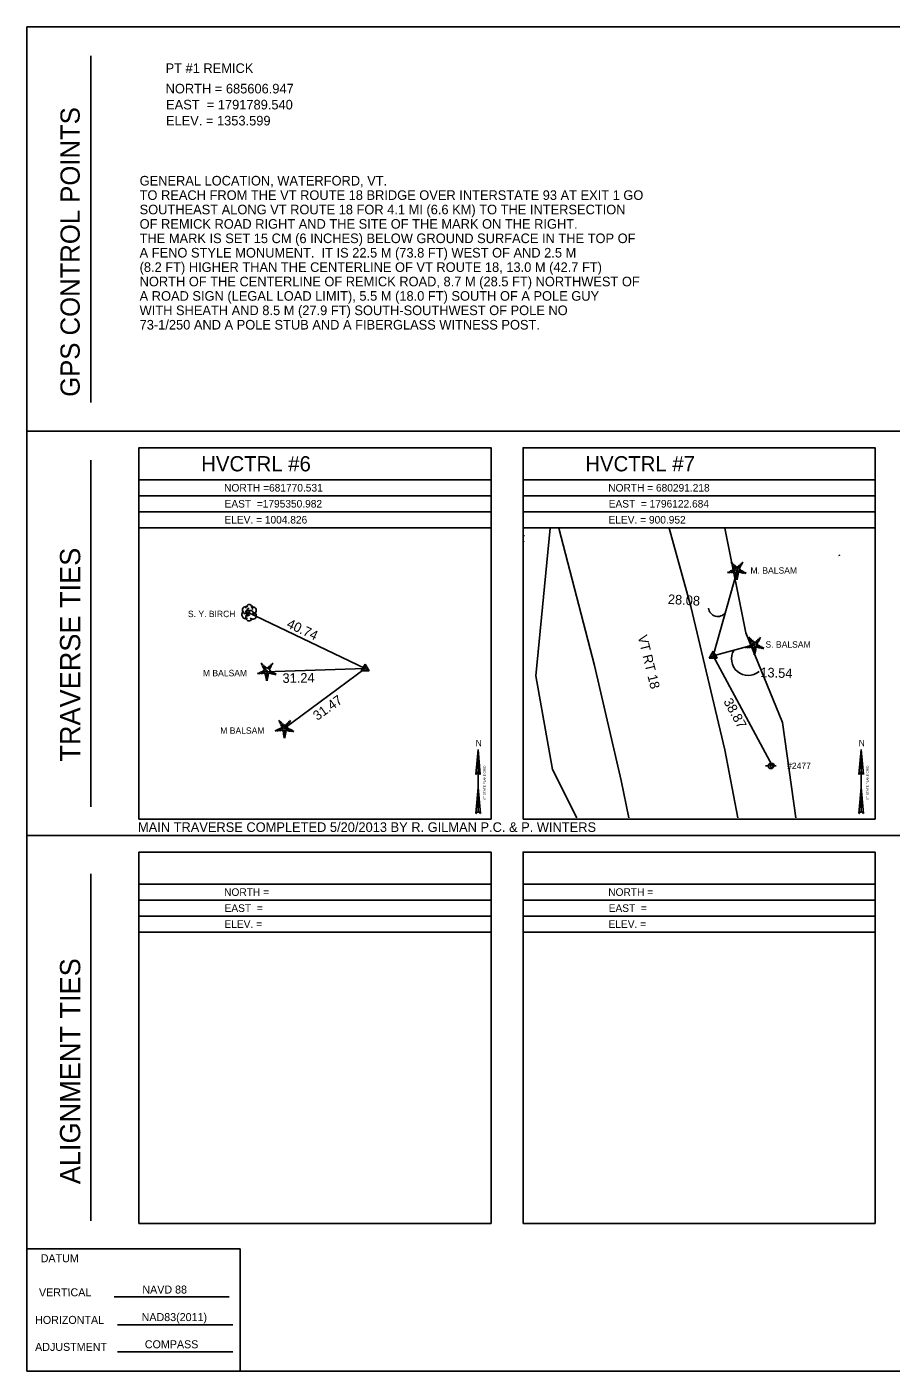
# Model space of a CAD drawing. Extents: x 1595203 to 1796102, y 680475 to 778796.
# Drawn here: x 1595203.1 to 1595473.1, y 778375.5 to 778795.5 of the extents above; entities that cross this region are included whole.
import ezdxf

# ---------------------------------------------------------------- set-up
doc = ezdxf.new("R2010")
doc.units = 0
for name, color, linetype in [('CBP', 7, 'Continuous'), ('CPSM', 7, 'Continuous'), ('Default', 7, 'Continuous'), ('L_C', 7, 'Continuous'), ('L_TIC', 7, 'Continuous'), ('LAWA', 7, 'Continuous'), ('LBF', 7, 'Continuous'), ('LTC', 7, 'Continuous'), ('LTD', 7, 'Continuous'), ('NBL1', 7, 'Continuous'), ('NBL2', 7, 'Continuous'), ('NNA_P', 7, 'Continuous'), ('PET', 7, 'Continuous'), ('RDG', 7, 'Continuous'), ('U_C', 7, 'Continuous'), ('UP', 7, 'Continuous')]:
    doc.layers.add(name, color=color, linetype=linetype)

msp = doc.modelspace()

# ---------------------------------------------------------------- linework, layer by layer
at = {"layer": 'CBP'}
for centre, radius in [((1595425.13, 778626.05), 0.625), ((1595425.13, 778626.05), 0.0833), ((1595272.02, 778612.64), 0.625), ((1595272.02, 778612.64), 0.0833), ((1595430.52, 778602.62), 0.625), ((1595430.52, 778602.62), 0.0833), ((1595277.54, 778594.03), 0.625), ((1595277.54, 778594.03), 0.0833), ((1595283.46, 778576.32), 0.625), ((1595283.46, 778576.32), 0.0833), ((1595435.87, 778564.8), 0.625), ((1595435.87, 778564.8), 0.0833)]:
    msp.add_circle(centre, radius, dxfattribs=at)
at = {"layer": 'CPSM'}
for p, q in [((1595416.21, 778598.32), (1595417.46, 778600.48)), ((1595418.71, 778598.32), (1595417.46, 778600.48)), ((1595417.46, 778599.04), (1595417.46, 778600.48)), ((1595307.51, 778594.31), (1595308.76, 778596.47)), ((1595310.01, 778594.31), (1595308.76, 778596.47)), ((1595308.77, 778595.03), (1595308.76, 778596.47)), ((1595416.21, 778598.32), (1595417.46, 778599.04)), ((1595416.21, 778598.32), (1595418.71, 778598.32)), ((1595417.46, 778599.04), (1595417.46, 778599.04)), ((1595417.46, 778599.04), (1595418.71, 778598.32)), ((1595307.51, 778594.31), (1595308.77, 778595.03)), ((1595307.51, 778594.31), (1595310.01, 778594.31)), ((1595308.77, 778595.03), (1595308.77, 778595.03)), ((1595308.77, 778595.03), (1595310.01, 778594.31))]:
    msp.add_line(p, q, dxfattribs=at)
at = {"layer": 'Default'}
for p, q in [((1595417.46, 778599.04), (1595425.13, 778626.05)), ((1595308.77, 778595.03), (1595272.02, 778612.64)), ((1595417.46, 778599.04), (1595430.52, 778602.62)), ((1595417.46, 778599.04), (1595435.87, 778564.8)), ((1595308.77, 778595.03), (1595277.54, 778594.03)), ((1595308.77, 778595.03), (1595283.46, 778576.32))]:
    msp.add_line(p, q, dxfattribs=at)
for centre, radius, start, end in [((1595418.93, 778614.18), 2.87, 184.4015, 325.3333), ((1595428.39, 778598.08), 5.19, 147.9758, 311.2903)]:
    msp.add_arc(centre, radius, start, end, dxfattribs=at)
at = {"layer": 'L_TIC'}
for points in [[(1595358.07, 778636.36), (1595358.39, 778636.69)], [(1595358.07, 778636.36), (1595358.39, 778636.69)], [(1595358.39, 778634.69), (1595358.07, 778635.01)], [(1595358.39, 778634.69), (1595358.07, 778635.01)]]:
    msp.add_lwpolyline(points, dxfattribs=at)
at = {"layer": 'LAWA'}
msp.add_lwpolyline([(1595421.15, 778638.92), (1595427.65, 778606.18), (1595439.14, 778578.24), (1595443.32, 778548.37)], dxfattribs=at)
at = {"layer": 'LBF'}
msp.add_lwpolyline([(1595456.93, 778630.23), (1595456.85, 778630.56)], dxfattribs=at)
at = {"layer": 'LTC'}
for p, q in [((1595422.51, 778625.53), (1595422.72, 778624.88)), ((1595422.96, 778625.75), (1595423.23, 778624.91)), ((1595423.02, 778628.03), (1595423.37, 778628.29)), ((1595423.23, 778627.57), (1595423.76, 778627.95)), ((1595423.42, 778625.96), (1595423.75, 778624.94)), ((1595423.44, 778627.1), (1595424.14, 778627.61)), ((1595423.65, 778626.64), (1595424.52, 778627.27)), ((1595423.87, 778626.18), (1595424.88, 778626.92)), ((1595423.87, 778626.18), (1595424.26, 778624.99)), ((1595424.88, 778626.92), (1595425.88, 778626.19)), ((1595425.3, 778627.23), (1595426.11, 778626.64)), ((1595425.88, 778626.19), (1595425.49, 778624.99)), ((1595425.67, 778627.58), (1595426.35, 778627.08)), ((1595426.32, 778625.92), (1595425.98, 778624.88)), ((1595426.04, 778627.93), (1595426.59, 778627.53)), ((1595426.42, 778628.27), (1595426.83, 778627.97)), ((1595426.76, 778625.67), (1595426.47, 778624.79)), ((1595427.21, 778625.42), (1595426.97, 778624.69)), ((1595422.05, 778625.31), (1595422.2, 778624.84)), ((1595425.49, 778624.99), (1595424.26, 778624.99)), ((1595425.45, 778624.49), (1595424.31, 778624.49)), ((1595425.37, 778623.99), (1595424.38, 778623.99)), ((1595425.28, 778623.49), (1595424.45, 778623.49)), ((1595425.2, 778622.99), (1595424.52, 778622.99)), ((1595427.65, 778625.17), (1595427.46, 778624.6)), ((1595428.56, 778604.57), (1595428.91, 778604.82)), ((1595428.77, 778604.1), (1595429.3, 778604.49)), ((1595431.59, 778604.46), (1595432.14, 778604.06)), ((1595431.96, 778604.81), (1595432.38, 778604.5)), ((1595427.59, 778601.85), (1595427.74, 778601.38)), ((1595428.05, 778602.06), (1595428.26, 778601.41)), ((1595428.5, 778602.28), (1595428.77, 778601.44)), ((1595428.96, 778602.5), (1595429.29, 778601.48)), ((1595428.98, 778603.64), (1595429.68, 778604.15)), ((1595429.19, 778603.17), (1595430.07, 778603.81)), ((1595429.41, 778602.72), (1595430.42, 778603.45)), ((1595429.41, 778602.72), (1595429.8, 778601.52)), ((1595431.03, 778601.52), (1595429.8, 778601.52)), ((1595430.99, 778601.02), (1595429.85, 778601.02)), ((1595430.91, 778600.52), (1595429.92, 778600.52)), ((1595430.42, 778603.45), (1595431.42, 778602.72)), ((1595430.84, 778603.76), (1595431.65, 778603.17)), ((1595431.42, 778602.72), (1595431.03, 778601.52)), ((1595431.22, 778604.11), (1595431.9, 778603.62)), ((1595431.86, 778602.45), (1595431.52, 778601.41)), ((1595432.3, 778602.2), (1595432.02, 778601.32)), ((1595432.75, 778601.95), (1595432.51, 778601.22)), ((1595433.19, 778601.7), (1595433.01, 778601.13)), ((1595276.17, 778596.46), (1595276.53, 778596.72)), ((1595276.38, 778596), (1595276.91, 778596.38)), ((1595276.59, 778595.53), (1595277.3, 778596.04)), ((1595278.83, 778596.01), (1595279.51, 778595.51)), ((1595279.2, 778596.35), (1595279.75, 778595.96)), ((1595279.57, 778596.7), (1595279.99, 778596.4)), ((1595430.82, 778600.02), (1595429.99, 778600.02)), ((1595430.74, 778599.52), (1595430.07, 778599.52)), ((1595275.21, 778593.74), (1595275.36, 778593.27)), ((1595275.66, 778593.96), (1595275.87, 778593.31)), ((1595276.12, 778594.17), (1595276.39, 778593.34)), ((1595276.57, 778594.39), (1595276.9, 778593.37)), ((1595276.8, 778595.07), (1595277.68, 778595.7)), ((1595277.03, 778594.61), (1595278.04, 778595.34)), ((1595277.03, 778594.61), (1595277.41, 778593.42)), ((1595278.64, 778593.42), (1595277.41, 778593.42)), ((1595278.61, 778592.92), (1595277.46, 778592.92)), ((1595278.52, 778592.42), (1595277.53, 778592.42)), ((1595278.44, 778591.92), (1595277.61, 778591.92)), ((1595278.04, 778595.34), (1595279.04, 778594.62)), ((1595278.46, 778595.66), (1595279.27, 778595.07)), ((1595279.04, 778594.62), (1595278.64, 778593.42)), ((1595279.47, 778594.35), (1595279.13, 778593.31)), ((1595279.92, 778594.1), (1595279.63, 778593.21)), ((1595280.36, 778593.85), (1595280.12, 778593.12)), ((1595280.81, 778593.6), (1595280.62, 778593.02)), ((1595278.35, 778591.42), (1595277.68, 778591.42)), ((1595280.75, 778575.86), (1595280.9, 778575.39)), ((1595281.21, 778576.08), (1595281.42, 778575.42)), ((1595281.66, 778576.29), (1595281.93, 778575.46)), ((1595281.72, 778578.58), (1595282.07, 778578.84)), ((1595281.93, 778578.12), (1595282.46, 778578.5)), ((1595282.12, 778576.51), (1595282.45, 778575.49)), ((1595282.14, 778577.65), (1595282.84, 778578.16)), ((1595282.35, 778577.18), (1595283.23, 778577.82)), ((1595282.57, 778576.73), (1595283.58, 778577.46)), ((1595282.57, 778576.73), (1595282.96, 778575.54)), ((1595284.19, 778575.54), (1595282.96, 778575.54)), ((1595284.15, 778575.04), (1595283.01, 778575.04)), ((1595283.58, 778577.46), (1595284.58, 778576.74)), ((1595284, 778577.78), (1595284.81, 778577.19)), ((1595284.58, 778576.74), (1595284.19, 778575.54)), ((1595284.37, 778578.12), (1595285.05, 778577.63)), ((1595285.02, 778576.47), (1595284.68, 778575.43)), ((1595284.75, 778578.47), (1595285.29, 778578.07)), ((1595285.12, 778578.82), (1595285.54, 778578.52)), ((1595285.46, 778576.22), (1595285.17, 778575.33)), ((1595285.91, 778575.97), (1595285.67, 778575.24)), ((1595286.35, 778575.72), (1595286.16, 778575.14)), ((1595284.07, 778574.54), (1595283.08, 778574.54)), ((1595283.98, 778574.04), (1595283.15, 778574.04)), ((1595283.9, 778573.54), (1595283.22, 778573.54))]:
    msp.add_line(p, q, dxfattribs=at)
at = {"layer": 'LTD'}
msp.add_line((1595272.47, 778612.55), (1595272.47, 778612.55), dxfattribs=at)
msp.add_line((1595272.47, 778612.55), (1595272.47, 778612.55), dxfattribs=at)
msp.add_arc((1595272.51, 778613.99), 1.05, 335.5272, 180.9563, dxfattribs=at)
for centre, major_axis, ratio, start_param, end_param in [((1595271.38, 778611.84), (0.58, -1.04), 0.959034, 3.141593, 6.283185), ((1595271.68, 778613.22), (1.21, -0.51), 0.895232, 1.570796, 4.712389), ((1595272.26, 778613.01), (-0.208, -0.792), 0.645439, 3.141593, 6.283185), ((1595272.97, 778612.39), (-0.5, 0.667), 0.989748, 3.141593, 6.283185), ((1595273.51, 778613.14), (-1.14, -0.48), 0.949671, 1.570796, 4.712389), ((1595272.47, 778611.05), (0.26, 1.06), 0.942809, 1.570796, 4.712389), ((1595272.01, 778611.8), (-0.625, -0.083), 0.423636, 0, 3.141593), ((1595273.47, 778611.72), (-1.09, 0.79), 0.841452, 1.570796, 4.712389)]:
    msp.add_ellipse(centre, major_axis=major_axis, ratio=ratio, start_param=start_param, end_param=end_param, dxfattribs=at)
at = {"layer": 'NBL1'}
msp.add_lwpolyline([(1595203.07, 778375.54), (1595843.07, 778375.54), (1595843.07, 778795.54), (1595203.07, 778795.54)], close=True, dxfattribs=at)
at = {"layer": 'NBL2'}
for p, q in [((1595223.07, 778678.21), (1595223.07, 778786.54)), ((1595203.07, 778669.21), (1595843.07, 778669.21)), ((1595223.07, 778551.88), (1595223.07, 778660.21)), ((1595348.07, 778654.04), (1595238.07, 778654.04)), ((1595468.07, 778654.04), (1595358.07, 778654.04)), ((1595348.07, 778649.04), (1595238.07, 778649.04)), ((1595468.07, 778649.04), (1595358.07, 778649.04)), ((1595348.07, 778644.04), (1595238.07, 778644.04)), ((1595468.07, 778644.04), (1595358.07, 778644.04)), ((1595348.07, 778639.04), (1595238.07, 778639.04)), ((1595468.07, 778639.04), (1595358.07, 778639.04)), ((1595203.07, 778542.88), (1595843.07, 778542.88)), ((1595223.07, 778422.54), (1595223.07, 778530.88)), ((1595348.07, 778527.71), (1595238.07, 778527.71)), ((1595468.07, 778527.71), (1595358.07, 778527.71)), ((1595348.07, 778522.71), (1595238.07, 778522.71)), ((1595468.07, 778522.71), (1595358.07, 778522.71)), ((1595348.07, 778517.71), (1595238.07, 778517.71)), ((1595468.07, 778517.71), (1595358.07, 778517.71)), ((1595348.07, 778512.71), (1595238.07, 778512.71)), ((1595468.07, 778512.71), (1595358.07, 778512.71)), ((1595269.74, 778413.79), (1595203.07, 778413.79)), ((1595269.74, 778413.79), (1595269.74, 778375.54)), ((1595269.74, 778413.79), (1595269.74, 778375.54)), ((1595230.31, 778398.77), (1595266.31, 778398.74)), ((1595231.42, 778390), (1595267.42, 778390)), ((1595231.42, 778381.56), (1595267.42, 778381.53))]:
    msp.add_line(p, q, dxfattribs=at)
for points in [[(1595238.07, 778548.04), (1595348.07, 778548.04), (1595348.07, 778664.04), (1595238.07, 778664.04)], [(1595358.07, 778548.04), (1595468.07, 778548.04), (1595468.07, 778664.04), (1595358.07, 778664.04)], [(1595238.07, 778421.71), (1595348.07, 778421.71), (1595348.07, 778537.71), (1595238.07, 778537.71)], [(1595358.07, 778421.71), (1595468.07, 778421.71), (1595468.07, 778537.71), (1595358.07, 778537.71)]]:
    msp.add_lwpolyline(points, close=True, dxfattribs=at)
at = {"layer": 'NNA_P'}
for p, q in [((1595343.33, 778562), (1595344.03, 778569.79)), ((1595344.03, 778550.42), (1595344.03, 778569.79)), ((1595344.72, 778562), (1595344.03, 778569.79)), ((1595463.01, 778562), (1595463.7, 778569.79)), ((1595463.71, 778550.42), (1595463.7, 778569.79)), ((1595464.4, 778562), (1595463.7, 778569.79)), ((1595343.33, 778562), (1595344.03, 778562.77)), ((1595344.72, 778562), (1595344.03, 778562.77)), ((1595463.01, 778562), (1595463.71, 778562.77)), ((1595464.4, 778562), (1595463.71, 778562.77)), ((1595344.03, 778557.94), (1595343.31, 778549.78)), ((1595344.03, 778557.94), (1595344.75, 778549.78)), ((1595463.71, 778557.94), (1595462.99, 778549.78)), ((1595463.71, 778557.94), (1595464.43, 778549.78)), ((1595344.03, 778550.42), (1595343.31, 778549.78)), ((1595344.03, 778550.42), (1595344.75, 778549.78)), ((1595463.71, 778550.42), (1595462.99, 778549.78)), ((1595463.71, 778550.42), (1595464.43, 778549.78))]:
    msp.add_line(p, q, dxfattribs=at)
at = {"layer": 'PET'}
for points in [[(1595369.28, 778638.92), (1595380.42, 778596.06), (1595388.76, 778560.04), (1595391.08, 778548.37)], [(1595403.69, 778638.92), (1595410.53, 778614.49), (1595421.08, 778569.69), (1595425.18, 778548.37)]]:
    msp.add_lwpolyline(points, dxfattribs=at)
at = {"layer": 'RDG'}
msp.add_lwpolyline([(1595366.55, 778638.92), (1595362.07, 778592.73), (1595367.27, 778563.53), (1595374.85, 778548.37)], dxfattribs=at)
at = {"layer": 'UP'}
for p, q in [((1595433.84, 778564.61), (1595434.67, 778564.61)), ((1595435.5, 778564.61), (1595435.5, 778564.61)), ((1595437.17, 778564.61), (1595436.33, 778564.61)), ((1595436.33, 778564.61), (1595436.33, 778564.61)), ((1595437.17, 778564.61), (1595437.17, 778564.61))]:
    msp.add_line(p, q, dxfattribs=at)
msp.add_circle((1595435.5, 778564.61), 0.833, dxfattribs=at)

# ---------------------------------------------------------------- texts
at = {"layer": 'Default'}
for s, p in [('GENERAL LOCATION, WATERFORD, VT. ', (1595238.29, 778745.98)), ('TO REACH FROM THE VT ROUTE 18 BRIDGE OVER INTERSTATE 93 AT EXIT 1 GO', (1595238.29, 778741.48)), ('SOUTHEAST ALONG VT ROUTE 18 FOR 4.1 MI (6.6 KM) TO THE INTERSECTION', (1595238.29, 778736.98)), ('OF REMICK ROAD RIGHT AND THE SITE OF THE MARK ON THE RIGHT. ', (1595238.29, 778732.48)), ('THE MARK IS SET 15 CM (6 INCHES) BELOW GROUND SURFACE IN THE TOP OF', (1595238.29, 778727.98)), ('A FENO STYLE MONUMENT.  IT IS 22.5 M (73.8 FT) WEST OF AND 2.5 M', (1595238.29, 778723.48)), ('(8.2 FT) HIGHER THAN THE CENTERLINE OF VT ROUTE 18, 13.0 M (42.7 FT)', (1595238.29, 778718.98)), ('NORTH OF THE CENTERLINE OF REMICK ROAD, 8.7 M (28.5 FT) NORTHWEST OF', (1595238.29, 778714.48)), ('A ROAD SIGN (LEGAL LOAD LIMIT), 5.5 M (18.0 FT) SOUTH OF A POLE GUY', (1595238.29, 778709.98)), ('WITH SHEATH AND 8.5 M (27.9 FT) SOUTH-SOUTHWEST OF POLE NO', (1595238.29, 778705.48)), ('73-1/250 AND A POLE STUB AND A FIBERGLASS WITNESS POST.', (1595238.29, 778700.98)), ('MAIN TRAVERSE COMPLETED 5/20/2013 BY R. GILMAN P.C. & P. WINTERS', (1595237.77, 778544.01))]:
    msp.add_text(s, height=3, dxfattribs=at).set_placement(p)
for s, rotation, p in [('28.08', 356.7281, (1595403.26, 778615.26)), ('40.74', 334.9489, (1595284, 778608.03)), ('VT RT 18', 283.8205, (1595393.89, 778605.11)), ('31.24', 0.8754, (1595282.94, 778590.56)), ('13.54', 357.8906, (1595432.16, 778592.4)), ('31.47', 35.7129, (1595293.81, 778578.68)), ('38.87', 298.8374, (1595420.6, 778584.78))]:
    msp.add_text(s, height=3, rotation=rotation, dxfattribs=at).set_placement(p)
at = {"layer": 'L_C'}
for s, p in [('M. BALSAM', (1595429.12, 778624.72)), ('S. Y. BIRCH', (1595253.38, 778611.12)), ('S. BALSAM', (1595433.82, 778601.59)), ('M BALSAM', (1595258.05, 778592.65)), ('M BALSAM', (1595263.48, 778574.67))]:
    msp.add_text(s, height=2, dxfattribs=at).set_placement(p)
at = {"layer": 'LTC'}
for p in [(1595424.76, 778625.93), (1595430.31, 778602.46), (1595277.92, 778594.36), (1595283.47, 778576.48)]:
    msp.add_text('.', height=1.04, rotation=270, dxfattribs=at).set_placement(p)
at = {"layer": 'NBL2'}
for s, height, p in [('PT #1 REMICK        ', 3, (1595246.41, 778781.13)), ('NORTH = 685606.947  ', 3, (1595246.41, 778774.75)), ('EAST  = 1791789.540 ', 3, (1595246.56, 778769.75)), ('ELEV. = 1353.599    ', 3, (1595246.52, 778764.75)), ('     HVCTRL #6     ', 4.75, (1595248.72, 778656.67)), ('     HVCTRL #7     ', 4.75, (1595368.72, 778656.67)), ('NORTH =681770.531   ', 2.375, (1595264.69, 778650.36)), ('NORTH = 680291.218  ', 2.375, (1595384.69, 778650.36)), ('EAST  =1795350.982  ', 2.375, (1595264.83, 778645.36)), ('EAST  = 1796122.684 ', 2.375, (1595384.83, 778645.36)), ('ELEV. = 1004.826    ', 2.375, (1595264.79, 778640.36)), ('ELEV. = 900.952     ', 2.375, (1595384.79, 778640.36)), ('NORTH =             ', 2.375, (1595264.69, 778524.02)), ('NORTH =             ', 2.375, (1595384.69, 778524.02)), ('EAST  =             ', 2.375, (1595264.83, 778519.02)), ('EAST  =             ', 2.375, (1595384.83, 778519.02)), ('ELEV. =             ', 2.375, (1595264.79, 778514.02)), ('ELEV. =             ', 2.375, (1595384.79, 778514.02)), ('DATUM', 2.5, (1595207.39, 778409.56)), ('  NAVD 88 ', 2.5, (1595237.29, 778399.78)), ('HORIZONTAL', 2.5, (1595205.64, 778390.29)), ('NAD83(2011)', 2.5, (1595238.92, 778391.17)), ('ADJUSTMENT', 2.5, (1595205.64, 778381.86)), ('  COMPASS ', 2.5, (1595238.06, 778382.68))]:
    msp.add_text(s, height=height, dxfattribs=at).set_placement(p)
for s, height, rotation, p in [('GPS CONTROL POINTS', 6, 90, (1595219.57, 778679.96)), ('TRAVERSE TIES', 6.3332, 90, (1595219.74, 778565.98)), ('ALIGNMENT TIES', 6.3332, 90, (1595219.74, 778433.95)), ('VERTICAL', 2.5, 0.1439, (1595206.85, 778398.89))]:
    msp.add_text(s, height=height, rotation=rotation, dxfattribs=at).set_placement(p)
at = {"layer": 'NNA_P'}
for p in [(1595343.26, 778570.8), (1595462.94, 778570.8)]:
    msp.add_text('N', height=1.97, dxfattribs=at).set_placement(p)
for p in [(1595346.38, 778553.98), (1595466.06, 778553.98)]:
    msp.add_text('VT STATE PLANE GRID', height=0.7, rotation=90.0204, dxfattribs=at).set_placement(p)
at = {"layer": 'U_C'}
msp.add_text('#2477', height=2, dxfattribs=at).set_placement((1595440.58, 778563.67))

doc.saveas('drawing.dxf')
